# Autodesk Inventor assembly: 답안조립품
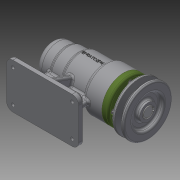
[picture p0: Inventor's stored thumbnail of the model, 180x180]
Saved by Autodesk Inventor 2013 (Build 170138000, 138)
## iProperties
Created: 2016-06
Part Number: 답안조립품
Document SubType Name: Assembly
Designer: Administrator
Author: Administrator
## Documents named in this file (12)
- C:\Users\Administrator\Desktop\460608V1011\답안조립품.iam
- C:\Users\Administrator\Desktop\460608V1011\본체.ipt
- C:\Users\Administrator\Desktop\460608V1011\베어링 6004.ipt
- C:\Users\Administrator\Desktop\460608V1011\볼트 M4 x 12.ipt
- C:\Users\Administrator\Desktop\460608V1011\오일 실.ipt
- C:\Users\Administrator\Desktop\460608V1011\커버.ipt
- C:\Users\Administrator\Desktop\460608V1011\축.ipt
- C:\Users\Administrator\Desktop\460608V1011\키 5 x 5 x 16.ipt
- C:\Users\Administrator\Desktop\460608V1011\V벨트풀리.ipt
- C:\Users\Administrator\Desktop\460608V1011\멈춤나사 M3x8.ipt
- C:\Users\Administrator\Desktop\460608V1011\어댑터슬리브.ipt
- C:\Users\Administrator\Desktop\460608V1011\베어링 51202.ipt
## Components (6 placed, 2 different names)
1. V벨트풀리:1
2. ISO 4762 M4 x 12:5 — 각도:3
3. ISO 4762 M4 x 12:1 — 각도:1
4. ISO 4762 M4 x 12:2
5. ISO 4762 M4 x 12:3
6. ISO 4762 M4 x 12:4
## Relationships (2: Angle 2)
- 각도:1 [Angle]: ISO 4762 M4 x 12:1
- 각도:3 [Angle]: ISO 4762 M4 x 12:5
